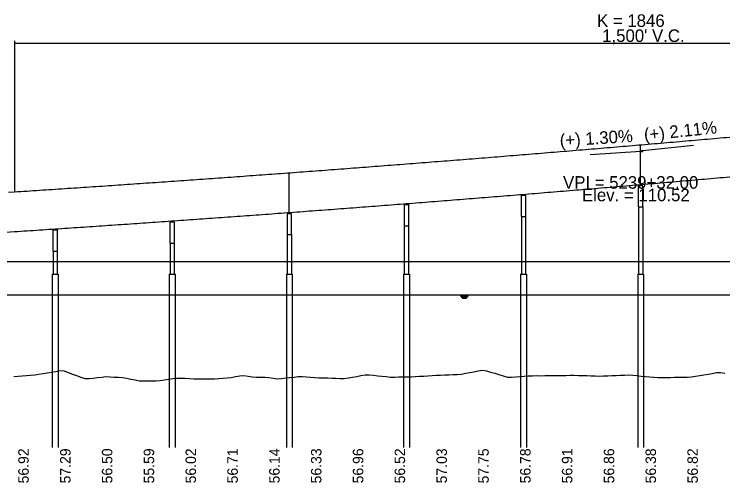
# Model space of a CAD drawing. Extents: x 2121671 to 2169879, y 557274 to 599957.
# Drawn here: x 2152750 to 2153597, y 595763 to 596324 of the extents above; entities that cross this region are included whole.
import ezdxf

# ---------------------------------------------------------------- set-up
doc = ezdxf.new("R2010")
doc.units = 0
for name, color, linetype in [('BR_CONCRETE', 7, 'Continuous'), ('BR_DETAILS', 7, 'Continuous'), ('BR_PRESTRESSED BEAM', 7, 'Continuous'), ('RD_DDB_GradeTX', 7, 'Continuous'), ('RD_DDB_Profile_Elev', 7, 'Continuous'), ('RD_DDB_Profile_EX', 7, 'Continuous'), ('RD_DDB_Profile_Lbl', 7, 'Continuous'), ('RD_DDB_Profile_PR', 7, 'Continuous'), ('RD_DDB_StripGrade', 7, 'Continuous'), ('RD_DDB_VCLbl', 7, 'Continuous')]:
    doc.layers.add(name, color=color, linetype=linetype)

msp = doc.modelspace()

# ---------------------------------------------------------------- linework, layer by layer
at = {"layer": 'BR_CONCRETE'}
for p, q in [((2153496.32, 596093.56), (2153496.32, 596013.07)), ((2153496.32, 596093.56), (2153496.32, 596013.07)), ((2153501.32, 596093.56), (2153501.32, 596013.07)), ((2153501.32, 596093.56), (2153501.32, 596013.07)), ((2153356.32, 596081.9), (2153356.32, 596013.07)), ((2153356.32, 596081.9), (2153356.32, 596013.07)), ((2153361.32, 596081.9), (2153361.32, 596013.07)), ((2153361.32, 596081.9), (2153361.32, 596013.07)), ((2153216.32, 596070.77), (2153216.32, 596013.07)), ((2153216.32, 596070.77), (2153216.32, 596013.07)), ((2153221.32, 596070.77), (2153221.32, 596013.07)), ((2153221.32, 596070.77), (2153221.32, 596013.07)), ((2153076.32, 596060.17), (2153076.32, 596013.07)), ((2153076.32, 596060.17), (2153076.32, 596013.07)), ((2153081.32, 596060.17), (2153081.32, 596013.07)), ((2153081.32, 596060.17), (2153081.32, 596013.07)), ((2152936.32, 596050.1), (2152936.32, 596013.07)), ((2152936.32, 596050.1), (2152936.32, 596013.07)), ((2152941.32, 596050.1), (2152941.32, 596013.07)), ((2152941.32, 596050.1), (2152941.32, 596013.07)), ((2152796.32, 596040.56), (2152796.32, 596013.07)), ((2152796.32, 596040.56), (2152796.32, 596013.07)), ((2152801.32, 596040.56), (2152801.32, 596013.07)), ((2152801.32, 596040.56), (2152801.32, 596013.07)), ((2152795.32, 596013.07), (2152795.32, 595805.78)), ((2152795.32, 596013.07), (2152795.32, 595805.78)), ((2152802.32, 596013.07), (2152802.32, 595805.78)), ((2152802.32, 596013.07), (2152802.32, 595805.78)), ((2152935.32, 596013.07), (2152935.32, 595805.78)), ((2152935.32, 596013.07), (2152935.32, 595805.78)), ((2152942.32, 596013.07), (2152942.32, 595805.78)), ((2152942.32, 596013.07), (2152942.32, 595805.78)), ((2153075.32, 596013.07), (2153075.32, 595805.78)), ((2153075.32, 596013.07), (2153075.32, 595805.78)), ((2153082.32, 596013.07), (2153082.32, 595805.78)), ((2153082.32, 596013.07), (2153082.32, 595805.78)), ((2153215.32, 596013.07), (2153215.32, 595805.78)), ((2153215.32, 596013.07), (2153215.32, 595805.78)), ((2153222.32, 596013.07), (2153222.32, 595805.78)), ((2153222.32, 596013.07), (2153222.32, 595805.78)), ((2153355.32, 596013.07), (2153355.32, 595805.78)), ((2153355.32, 596013.07), (2153355.32, 595805.78)), ((2153362.32, 596013.07), (2153362.32, 595805.78)), ((2153362.32, 596013.07), (2153362.32, 595805.78)), ((2153495.32, 596013.07), (2153495.32, 595805.78)), ((2153495.32, 596013.07), (2153495.32, 595805.78)), ((2153502.32, 596013.07), (2153502.32, 595805.78)), ((2153502.32, 596013.07), (2153502.32, 595805.78))]:
    msp.add_line(p, q, dxfattribs=at)
for points in [[(2153496.07, 596093.56), (2153501.57, 596093.56), (2153501.57, 596118.56), (2153496.07, 596118.56)], [(2153496.07, 596093.56), (2153501.57, 596093.56), (2153501.57, 596118.56), (2153496.07, 596118.56)], [(2153356.07, 596081.9), (2153361.57, 596081.9), (2153361.57, 596106.9), (2153356.07, 596106.9)], [(2153356.07, 596081.9), (2153361.57, 596081.9), (2153361.57, 596106.9), (2153356.07, 596106.9)], [(2153216.07, 596070.77), (2153221.57, 596070.77), (2153221.57, 596095.77), (2153216.07, 596095.77)], [(2153216.07, 596070.77), (2153221.57, 596070.77), (2153221.57, 596095.77), (2153216.07, 596095.77)], [(2153076.07, 596060.17), (2153081.57, 596060.17), (2153081.57, 596085.17), (2153076.07, 596085.17)], [(2153076.07, 596060.17), (2153081.57, 596060.17), (2153081.57, 596085.17), (2153076.07, 596085.17)], [(2152936.07, 596050.1), (2152941.57, 596050.1), (2152941.57, 596075.1), (2152936.07, 596075.1)], [(2152936.07, 596050.1), (2152941.57, 596050.1), (2152941.57, 596075.1), (2152936.07, 596075.1)], [(2152796.07, 596040.56), (2152801.57, 596040.56), (2152801.57, 596065.56), (2152796.07, 596065.56)], [(2152796.07, 596040.56), (2152801.57, 596040.56), (2152801.57, 596065.56), (2152796.07, 596065.56)]]:
    msp.add_lwpolyline(points, close=True, dxfattribs=at)
at = {"layer": 'BR_DETAILS'}
for points in [[(2153497.32, 596119.81), (2153498.32, 596119.81), (2153498.32, 596118.56), (2153497.32, 596118.56)], [(2153497.32, 596119.81), (2153498.32, 596119.81), (2153498.32, 596118.56), (2153497.32, 596118.56)], [(2153499.32, 596119.81), (2153500.32, 596119.81), (2153500.32, 596118.56), (2153499.32, 596118.56)], [(2153499.32, 596119.81), (2153500.32, 596119.81), (2153500.32, 596118.56), (2153499.32, 596118.56)], [(2153357.32, 596108.15), (2153358.32, 596108.15), (2153358.32, 596106.9), (2153357.32, 596106.9)], [(2153357.32, 596108.15), (2153358.32, 596108.15), (2153358.32, 596106.9), (2153357.32, 596106.9)], [(2153359.32, 596108.15), (2153360.32, 596108.15), (2153360.32, 596106.9), (2153359.32, 596106.9)], [(2153359.32, 596108.15), (2153360.32, 596108.15), (2153360.32, 596106.9), (2153359.32, 596106.9)], [(2153217.32, 596097.02), (2153218.32, 596097.02), (2153218.32, 596095.77), (2153217.32, 596095.77)], [(2153217.32, 596097.02), (2153218.32, 596097.02), (2153218.32, 596095.77), (2153217.32, 596095.77)], [(2153219.32, 596097.02), (2153220.32, 596097.02), (2153220.32, 596095.77), (2153219.32, 596095.77)], [(2153219.32, 596097.02), (2153220.32, 596097.02), (2153220.32, 596095.77), (2153219.32, 596095.77)], [(2153077.32, 596086.42), (2153078.32, 596086.42), (2153078.32, 596085.17), (2153077.32, 596085.17)], [(2153077.32, 596086.42), (2153078.32, 596086.42), (2153078.32, 596085.17), (2153077.32, 596085.17)], [(2153079.32, 596086.42), (2153080.32, 596086.42), (2153080.32, 596085.17), (2153079.32, 596085.17)], [(2153079.32, 596086.42), (2153080.32, 596086.42), (2153080.32, 596085.17), (2153079.32, 596085.17)], [(2152937.32, 596076.35), (2152938.32, 596076.35), (2152938.32, 596075.1), (2152937.32, 596075.1)], [(2152937.32, 596076.35), (2152938.32, 596076.35), (2152938.32, 596075.1), (2152937.32, 596075.1)], [(2152939.32, 596076.35), (2152940.32, 596076.35), (2152940.32, 596075.1), (2152939.32, 596075.1)], [(2152939.32, 596076.35), (2152940.32, 596076.35), (2152940.32, 596075.1), (2152939.32, 596075.1)], [(2152797.32, 596066.81), (2152798.32, 596066.81), (2152798.32, 596065.56), (2152797.32, 596065.56)], [(2152797.32, 596066.81), (2152798.32, 596066.81), (2152798.32, 596065.56), (2152797.32, 596065.56)], [(2152799.32, 596066.81), (2152800.32, 596066.81), (2152800.32, 596065.56), (2152799.32, 596065.56)], [(2152799.32, 596066.81), (2152800.32, 596066.81), (2152800.32, 596065.56), (2152799.32, 596065.56)]]:
    msp.add_lwpolyline(points, close=True, dxfattribs=at)
at = {"layer": 'BR_PRESTRESSED BEAM'}
for p, q in [((2153498.82, 596119.94), (2153498.82, 596167.44)), ((2153498.82, 596119.94), (2153498.82, 596167.44)), ((2153078.82, 596086.53), (2153078.82, 596134.03)), ((2153078.82, 596086.53), (2153078.82, 596134.03)), ((2152311.74, 596035.32), (2152750.24, 596063.82)), ((2152311.74, 596035.32), (2152750.24, 596063.82)), ((2152795.32, 596013.07), (2152802.32, 596013.07)), ((2152795.32, 596013.07), (2152802.32, 596013.07)), ((2152935.32, 596013.07), (2152942.32, 596013.07)), ((2152935.32, 596013.07), (2152942.32, 596013.07)), ((2153075.32, 596013.07), (2153082.32, 596013.07)), ((2153075.32, 596013.07), (2153082.32, 596013.07)), ((2153215.32, 596013.07), (2153222.32, 596013.07)), ((2153215.32, 596013.07), (2153222.32, 596013.07)), ((2153355.32, 596013.07), (2153362.32, 596013.07)), ((2153355.32, 596013.07), (2153362.32, 596013.07)), ((2153495.32, 596013.07), (2153502.32, 596013.07)), ((2153495.32, 596013.07), (2153502.32, 596013.07))]:
    msp.add_line(p, q, dxfattribs=at)
msp.add_spline([(2152750.24, 596063.82), (2152780.24, 596065.79), (2152810.24, 596067.77), (2152840.24, 596069.78), (2152870.24, 596071.82), (2152900.24, 596073.88), (2152930.24, 596075.96), (2152960.24, 596078.07), (2152990.24, 596080.2), (2153020.24, 596082.36), (2153050.24, 596084.54), (2153080.24, 596086.75), (2153110.24, 596088.98), (2153140.24, 596091.23), (2153170.24, 596093.51), (2153200.24, 596095.82), (2153230.24, 596098.14), (2153260.24, 596100.5), (2153290.24, 596102.87), (2153320.24, 596105.27), (2153350.24, 596107.7), (2153380.24, 596110.15), (2153410.24, 596112.62), (2153440.24, 596115.12), (2153470.24, 596117.65), (2153500.24, 596120.19), (2153530.24, 596122.76), (2153560.24, 596125.36), (2153590.24, 596127.98), (2153620.24, 596130.63), (2153650.24, 596133.29), (2153680.24, 596135.99), (2153710.24, 596138.71), (2153740.24, 596141.45), (2153770.24, 596144.22), (2153800.24, 596147.01), (2153830.24, 596149.82), (2153860.24, 596152.66), (2153890.24, 596155.53), (2153920.24, 596158.41), (2153950.24, 596161.33), (2153980.24, 596164.26), (2154010.24, 596167.23), (2154040.24, 596170.21), (2154070.24, 596173.22), (2154100.24, 596176.26), (2154130.24, 596179.32), (2154160.24, 596182.4), (2154190.24, 596185.51), (2154220.24, 596188.64), (2154250.24, 596191.8)], degree=3, dxfattribs=at)
msp.add_spline([(2152750.24, 596063.82), (2152780.24, 596065.79), (2152810.24, 596067.77), (2152840.24, 596069.78), (2152870.24, 596071.82), (2152900.24, 596073.88), (2152930.24, 596075.96), (2152960.24, 596078.07), (2152990.24, 596080.2), (2153020.24, 596082.36), (2153050.24, 596084.54), (2153080.24, 596086.75), (2153110.24, 596088.98), (2153140.24, 596091.23), (2153170.24, 596093.51), (2153200.24, 596095.82), (2153230.24, 596098.14), (2153260.24, 596100.5), (2153290.24, 596102.87), (2153320.24, 596105.27), (2153350.24, 596107.7), (2153380.24, 596110.15), (2153410.24, 596112.62), (2153440.24, 596115.12), (2153470.24, 596117.65), (2153500.24, 596120.19), (2153530.24, 596122.76), (2153560.24, 596125.36), (2153590.24, 596127.98), (2153620.24, 596130.63), (2153650.24, 596133.29), (2153680.24, 596135.99), (2153710.24, 596138.71), (2153740.24, 596141.45), (2153770.24, 596144.22), (2153800.24, 596147.01), (2153830.24, 596149.82), (2153860.24, 596152.66), (2153890.24, 596155.53), (2153920.24, 596158.41), (2153950.24, 596161.33), (2153980.24, 596164.26), (2154010.24, 596167.23), (2154040.24, 596170.21), (2154070.24, 596173.22), (2154100.24, 596176.26), (2154130.24, 596179.32), (2154160.24, 596182.4), (2154190.24, 596185.51), (2154220.24, 596188.64), (2154250.24, 596191.8)], degree=3, dxfattribs=at)
at = {"layer": 'RD_DDB_GradeTX'}
for p, q in [((2153561.9, 596166.59), (2153501.24, 596160.18)), ((2153438.38, 596156.05), (2153499.25, 596160.01))]:
    msp.add_line(p, q, dxfattribs=at)
msp.add_circle((2153500.24, 596160.07), 1, dxfattribs=at)
at = {"layer": 'RD_DDB_Profile_Elev'}
for p, q in [((2151940.69, 596028.07), (2155629.71, 596028.07)), ((2151971.97, 595988.07), (2156334.94, 595988.07)), ((2153282.99, 595986.82), (2153292.99, 595986.82)), ((2153284.24, 595985.57), (2153291.74, 595985.57)), ((2153285.49, 595984.32), (2153290.49, 595984.32))]:
    msp.add_line(p, q, dxfattribs=at)
at = {"layer": 'RD_DDB_Profile_EX'}
for points in [[(2152749.48, 595890.41), (2152754.48, 595890.85), (2152759.48, 595891.29), (2152764.48, 595891.72), (2152769.48, 595892.16), (2152774.48, 595892.59), (2152779.48, 595893.18), (2152784.48, 595894.05), (2152789.48, 595894.92), (2152794.48, 595895.78), (2152799.48, 595896.65), (2152804.48, 595897.52), (2152809.48, 595897.13), (2152814.48, 595895.3), (2152819.48, 595893.47), (2152824.48, 595891.64), (2152829.48, 595889.81), (2152834.48, 595887.98), (2152839.48, 595888.11), (2152844.48, 595888.68), (2152849.48, 595889.26), (2152854.48, 595889.83), (2152859.48, 595890.37), (2152864.48, 595890.14), (2152869.48, 595889.91), (2152874.48, 595889.68), (2152879.48, 595889.45), (2152884.48, 595888.49), (2152889.48, 595887.43), (2152894.48, 595886.37), (2152899.48, 595885.31), (2152904.48, 595885.18), (2152909.48, 595885.27), (2152914.48, 595885.36), (2152919.48, 595885.45), (2152924.48, 595885.89), (2152929.48, 595886.63), (2152934.48, 595887.36), (2152939.48, 595888.1), (2152944.48, 595888.52), (2152949.48, 595888.44), (2152954.48, 595888.37), (2152959.48, 595888.29), (2152964.48, 595887.55), (2152969.48, 595887.6), (2152974.48, 595887.65), (2152979.48, 595887.71), (2152984.48, 595887.71), (2152989.48, 595887.69), (2152994.48, 595888.06), (2152999.48, 595888.42), (2153004.48, 595888.78), (2153009.48, 595889.46), (2153014.48, 595890.34), (2153019.48, 595891.22), (2153024.48, 595891.75), (2153029.48, 595891.03), (2153034.48, 595890.31), (2153039.48, 595889.58), (2153044.48, 595889.9), (2153049.48, 595889.87), (2153054.48, 595889.21), (2153059.48, 595888.55), (2153064.48, 595887.89), (2153069.48, 595888.27), (2153074.48, 595888.81), (2153079.48, 595889.35), (2153084.48, 595889.9), (2153089.48, 595890.37), (2153094.48, 595890.48), (2153099.48, 595890.14), (2153104.48, 595889.8), (2153109.48, 595889.46), (2153114.48, 595889.12), (2153119.48, 595889.11), (2153124.48, 595888.87), (2153129.48, 595888.62), (2153134.48, 595888.38), (2153139.48, 595888.14), (2153144.48, 595888), (2153149.48, 595888.85), (2153154.48, 595889.74), (2153159.48, 595890.64), (2153164.48, 595891.57), (2153169.48, 595892.53), (2153174.48, 595892.55), (2153179.48, 595892.01), (2153184.48, 595891.48), (2153189.48, 595890.94), (2153194.48, 595890.41)], [(2153194.48, 595890.41), (2153199.48, 595889.8), (2153204.48, 595889.84), (2153209.48, 595889.93), (2153214.48, 595890.02), (2153219.48, 595890.1), (2153224.48, 595890.19), (2153229.48, 595890.43), (2153234.48, 595890.75), (2153239.48, 595891.08), (2153244.48, 595891.4), (2153249.48, 595891.73), (2153254.48, 595892.11), (2153259.48, 595892.3), (2153264.48, 595892.5), (2153269.48, 595892.69), (2153274.48, 595892.88), (2153279.48, 595893.07), (2153284.48, 595893.4), (2153289.48, 595894.33), (2153294.48, 595895.26), (2153299.48, 595896.19), (2153304.48, 595897.13), (2153309.48, 595898.06), (2153314.48, 595897.34), (2153319.48, 595895.85), (2153324.48, 595894.36), (2153329.48, 595892.87), (2153334.48, 595891.38), (2153339.48, 595889.89), (2153344.48, 595889.83), (2153349.48, 595890.16), (2153354.48, 595890.48), (2153359.48, 595890.8), (2153364.48, 595891.12), (2153369.48, 595891.44), (2153374.48, 595891.76), (2153379.48, 595891.51), (2153384.48, 595891.57), (2153389.48, 595891.62), (2153394.48, 595891.68), (2153399.48, 595891.73), (2153404.48, 595891.79), (2153409.48, 595891.84), (2153414.48, 595892.12), (2153419.48, 595891.98), (2153424.48, 595891.83), (2153429.48, 595891.68), (2153434.48, 595891.54), (2153439.48, 595891.39), (2153444.48, 595891.24), (2153449.48, 595891.09), (2153454.48, 595891.26), (2153459.48, 595891.45), (2153464.48, 595891.64), (2153469.48, 595891.82), (2153474.48, 595892.01), (2153479.48, 595892.19), (2153484.48, 595892.35), (2153489.48, 595891.97), (2153494.48, 595891.52), (2153499.48, 595891.07), (2153504.48, 595890.62), (2153509.48, 595890.18), (2153514.48, 595889.73), (2153519.48, 595889.28), (2153524.48, 595889.26), (2153529.48, 595889.35), (2153534.48, 595889.43), (2153539.48, 595889.52), (2153544.48, 595889.6), (2153549.48, 595889.69), (2153554.48, 595889.78), (2153559.48, 595890.14), (2153564.48, 595890.96), (2153569.48, 595891.79), (2153574.48, 595892.62), (2153579.48, 595893.45), (2153584.48, 595894.28), (2153589.48, 595895.1), (2153594.48, 595895.41), (2153599.48, 595894.64)]]:
    msp.add_lwpolyline(points, dxfattribs=at)
at = {"layer": 'RD_DDB_Profile_PR'}
msp.add_line((2152743.15, 596110.87), (2152750.24, 596111.33), dxfattribs=at)
msp.add_spline([(2152750.24, 596111.33), (2152780.24, 596113.29), (2152810.24, 596115.28), (2152840.24, 596117.29), (2152870.24, 596119.32), (2152900.24, 596121.38), (2152930.24, 596123.47), (2152960.24, 596125.57), (2152990.24, 596127.71), (2153020.24, 596129.86), (2153050.24, 596132.05), (2153080.24, 596134.25), (2153110.24, 596136.48), (2153140.24, 596138.74), (2153170.24, 596141.02), (2153200.24, 596143.32), (2153230.24, 596145.65), (2153260.24, 596148), (2153290.24, 596150.38), (2153320.24, 596152.78), (2153350.24, 596155.2), (2153380.24, 596157.65), (2153410.24, 596160.13), (2153440.24, 596162.62), (2153470.24, 596165.15), (2153500.24, 596167.69), (2153530.24, 596170.27), (2153560.24, 596172.86), (2153590.24, 596175.48), (2153620.24, 596178.13), (2153650.24, 596180.8), (2153680.24, 596183.49), (2153710.24, 596186.21), (2153740.24, 596188.95), (2153770.24, 596191.72), (2153800.24, 596194.51), (2153830.24, 596197.32), (2153860.24, 596200.16), (2153890.24, 596203.03), (2153920.24, 596205.91), (2153950.24, 596208.83), (2153980.24, 596211.76), (2154010.24, 596214.73), (2154040.24, 596217.71), (2154070.24, 596220.72), (2154100.24, 596223.76), (2154130.24, 596226.82), (2154160.24, 596229.9), (2154190.24, 596233.01), (2154220.24, 596236.14), (2154250.24, 596239.3)], degree=3, dxfattribs=at)
at = {"layer": 'RD_DDB_VCLbl'}
for p, q in [((2152750.24, 596291.8), (2152750.24, 596111.33)), ((2152750.24, 596289.3), (2154250.24, 596289.3))]:
    msp.add_line(p, q, dxfattribs=at)

# ---------------------------------------------------------------- texts
at = {"layer": 'RD_DDB_GradeTX'}
for s, rotation, p in [('(+) 2.11%', 6.02987, (2153503.61, 596172.09)), ('(+) 1.30%', 3.71869, (2153402.58, 596165.33))]:
    msp.add_text(s, height=15, rotation=rotation, dxfattribs=at).set_placement(p)
at = {"layer": 'RD_DDB_Profile_Lbl'}
for s, p in [('VPI = 5239+32.00', (2153406.09, 596115.07)), ('Elev. = 110.52', (2153428.72, 596100.07))]:
    msp.add_text(s, height=15, dxfattribs=at).set_placement(p)
at = {"layer": 'RD_DDB_StripGrade'}
for s, p in [('56.92', (2152767.24, 595762.7)), ('57.29', (2152817.24, 595762.7)), ('56.50', (2152867.24, 595762.7)), ('55.59', (2152917.24, 595762.7)), ('56.02', (2152967.24, 595762.7)), ('56.71', (2153017.24, 595762.7)), ('56.14', (2153067.24, 595762.7)), ('56.33', (2153117.24, 595762.7)), ('56.96', (2153167.24, 595762.7)), ('56.52', (2153217.24, 595762.7)), ('57.03', (2153267.24, 595762.7)), ('57.75', (2153317.24, 595762.7)), ('56.78', (2153367.24, 595762.7)), ('56.91', (2153417.24, 595762.7)), ('56.86', (2153467.24, 595762.7)), ('56.38', (2153517.24, 595762.7)), ('56.82', (2153567.24, 595762.7))]:
    msp.add_text(s, height=12.5, rotation=90, dxfattribs=at).set_placement(p)
at = {"layer": 'RD_DDB_VCLbl'}
for s, p in [('K = 1846', (2153446.72, 596308.55)), ("1,500' V.C.", (2153452.88, 596290.55))]:
    msp.add_text(s, height=15, dxfattribs=at).set_placement(p)

doc.saveas('drawing.dxf')
